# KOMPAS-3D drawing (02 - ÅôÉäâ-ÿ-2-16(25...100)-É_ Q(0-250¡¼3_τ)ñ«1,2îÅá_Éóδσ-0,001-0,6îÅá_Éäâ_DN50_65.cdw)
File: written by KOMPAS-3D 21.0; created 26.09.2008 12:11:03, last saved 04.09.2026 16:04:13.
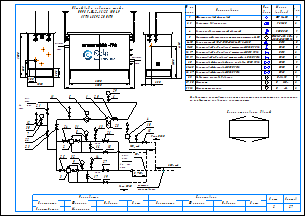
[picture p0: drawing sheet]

Sheets 1-2: A3, landscape

Document properties: Наименование: Макро:21; Автор: RaskoAdmin; Форматы листов документа: 2xA3; Полное имя файла: \\ur38nt01\Departments\КТО\КБ ПУРДГ\Заявки\Прайс-лист на типовые шкафы ГРПШ\ПУРДГ_стандарт_30_04_2026\ПУРДГ с РДГ(Н, В)\ПУРДГ-Ш-2-16(25...100)-Р_ Q(0-250нм3_ч)до1,2МПа_Рвых-0,001-0,6МПа_РДГ_DN50_65.cdw

Title block, sheet 1: Наименование: Пункт учета газа / ПУГ-Ш-400-Р / ЛГТИ.485922.001ТУ; designation: ЛГТИ.03.4411141; sheet number: 1; Количество листов документа: 2; organisation: ООО "ЭЛЬСТЕР Газэлектроника"; Форматы листов документа: A3; stored path: C:\Рабочие документы\Компас\ПУГ\Схема.cdw; Разработал: Устинов; Проверил: Кошкин; Утвердил: Кошкин
Title block, sheet 2: sheet number: 2; stored path: D:\Рабочие документы\Заявки\ПУРДГ\ПУРДГ-ШУЭО-2-100-Р 4411220.cdw; designation, second copy: ЛГТИ.03.4411141-

Views: Вид 1, Вид 2
Referenced files: wcvoit.frw
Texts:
  Normal
  № на
  схеме
  Усл.
  обозн.
  Марка
  (модель)
  Кол.
  Фильтр газовый фланцевый
  ФГ 16-50
  Регулятор давления газа
  РДГ-50
  Клапан предохранительный сбросной
  КПС DN20
  Измерительный комплекс с ротационным счетчиком Ду50
  СГ-ЭК-Р-(0,2...2,0)-
  Кран кнопочный VE-РАСКО-НЗ-1,6-G1/2-М20
  DN15
  Кран шаровой "под приварку" штуцерный DN20 PN16
  DN20
  Кран шаровой "под приварку" штуцерный DN15 PN16
  Кран шаровой "под приварку" штуцерный п/п DN20 PN16
  Кран шаровой фланцевый с мех. приводом DN50 PN16
  Кран шаровой фланцевый DN50 PN16
  Кран шаровой фланцевый DN65 PN16
  DN50
  DN65
  Индикатор перепада давления
  Манометр
  Манометр-напоромер
  Delta 15
  0...     МПа
  0...     кПа
  Общий вид и габариты шкафа
  ПУРДГ-Ш-2-16(25...100)-Р
  Выход газа
  Вход газа
  logo-rasko-ge.png
  DN 1
  местное
  сопротивление
  Римп DN20
  Выход
  газа
  Р=     кПа
  Вход
  Р=       МПа
  PDI
  Схема открывания дверей
  Предприятие изготовитель может заменять комплектующие на аналогичные,
  не ухудшающие заявленных характеристик.
  Должность
  Конструктор
  Фамилия
  Подпись
  Дата
  Согласовано
  Максимкин
  Лист
  Листов
  POLYLINE_STYLE_0.18_RGB_0_0_0
  POLYLINE_STYLE_0.50_RGB_0_0_0
  POLYLINE_STYLE_0.34_RGB_0_0_0
  PHANTOM_RGB_0_0_0_SC_1_THICK_0.18
  K5LT_THIN_RGB_0_0_0_THICK_0.18
  K5LT32769_RGB_0_0_0_THICK_0.18
  K5LT12_RGB_0_0_0_SC_1_THICK_0.18
  K5LT_DASHED_RGB_0_0_0_SC_1_THICK_0.18
  ACISOTGL_RGB_0_0_0_SC_0.8_THICK_0.25
  CONTINUOUS_RGB_0_127_31_THICK_0.3
  CONTINUOUS_RGB_0_0_255_THICK_0.35
  CONTINUOUS_RGB_255_0_0_THICK_0.35
  POLYLINE_STYLE_0.25_RGB_0_0_0
  CONTINUOUS_RGB_0_0_0_THICK_0.5
  POLYLINE_STYLE_0.35_RGB_0_0_255
  CONTINUOUS_RGB_0_0_0_THICK_0.4
  CONTINUOUS_RGB_0_0_0_THICK_0.35
  НЕВИДИМАЯ_RGB_0_0_0_SC_0.3_THICK_0.25
  СONTINUOUS_RGB_0_0_0_THICK_0.25
  ОСЕВАЯ2_RGB_248_153_30_SC_0.3_THICK_0.25
  Без оформления
Dimensions and other numbers on the sheet: 1; 2, 3; 2; 4; 5; 6-10; 11-15; 16, 17; 18, 19; 20; 21-25; 26, 27; 28; 29, 30; 31, 32; 1500; 250; 300; 1050; 550; 305; 2500; 4130; 2000; 2800; 5,,,7DN 1; 7; 30; 12; 21; 22; 23; 11; 6; 29; 24; 31; 8; 13; 26; 18; 10; 15; 25; 32; 9; 3; 14; 27; 19; 16; 17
